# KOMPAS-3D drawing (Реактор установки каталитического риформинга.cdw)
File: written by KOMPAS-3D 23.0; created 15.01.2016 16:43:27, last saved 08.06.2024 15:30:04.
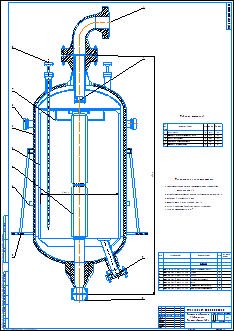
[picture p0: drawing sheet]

Sheet 1: A1, portrait

Document properties: Автор: pc; Наименование: Реактор гидроочистки установки Л-35-11/1000; Полное имя файла: G:\Учёба\Курсовое проектирование\Курсовой проект 4 курс\Гатауллин Эдик Л-35-5\Диплом риформинг Эдик\Реактор риформинг\Для публикации\Реактор установки каталитического риформинга.cdw

Title block, sheet 1: Наименование: Реактор гидроочистки / установки Л-35-11/1000.; scale: 1:20; Количество листов документа: 1; Форматы листов документа: A1; stored path: C:\Users\pc\Desktop\Работа\34 Элина Азаматовна\Реактор гидроочистки установки Л-24-5..cdw; designation, second copy: УТЭК.18.02.09.КП.09.00.000.СЗ-; Разработал: Низаева Э.А; Проверил: Пономарева Л.Ф

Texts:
  Материал-Предприятие
  Лит-Масса-Масштаб
  Normal
  K5LT32768_RGB_0_0_255_THICK_0.18
  POLYLINE_STYLE_0.18_RGB_0_0_255
  K5LT32769_RGB_0_0_0_THICK_0.18
  K5LT32770_RGB_255_127_0_SC_1_THICK_0.18
  POLYLINE_STYLE_0.18_RGB_0_0_0
  K5LT32772_RGB_0_0_0_SC_1_THICK_0.18
  K5LT_BASIC_RGB_0_0_255_THICK_0.6
  K5LT32771_RGB_0_0_0_THICK_0.18
  K5LT_THIN_RGB_0_0_0_THICK_0.18
  штрихпунктирная2_RGB_0_0_0_SC_1_THICK_0.2
  осевая2_RGB_0_0_0_SC_1_THICK_0.2
  МЕТАЛЛ_ANSI_ISO
Dimensions and other numbers on the sheet: 1:20; 1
